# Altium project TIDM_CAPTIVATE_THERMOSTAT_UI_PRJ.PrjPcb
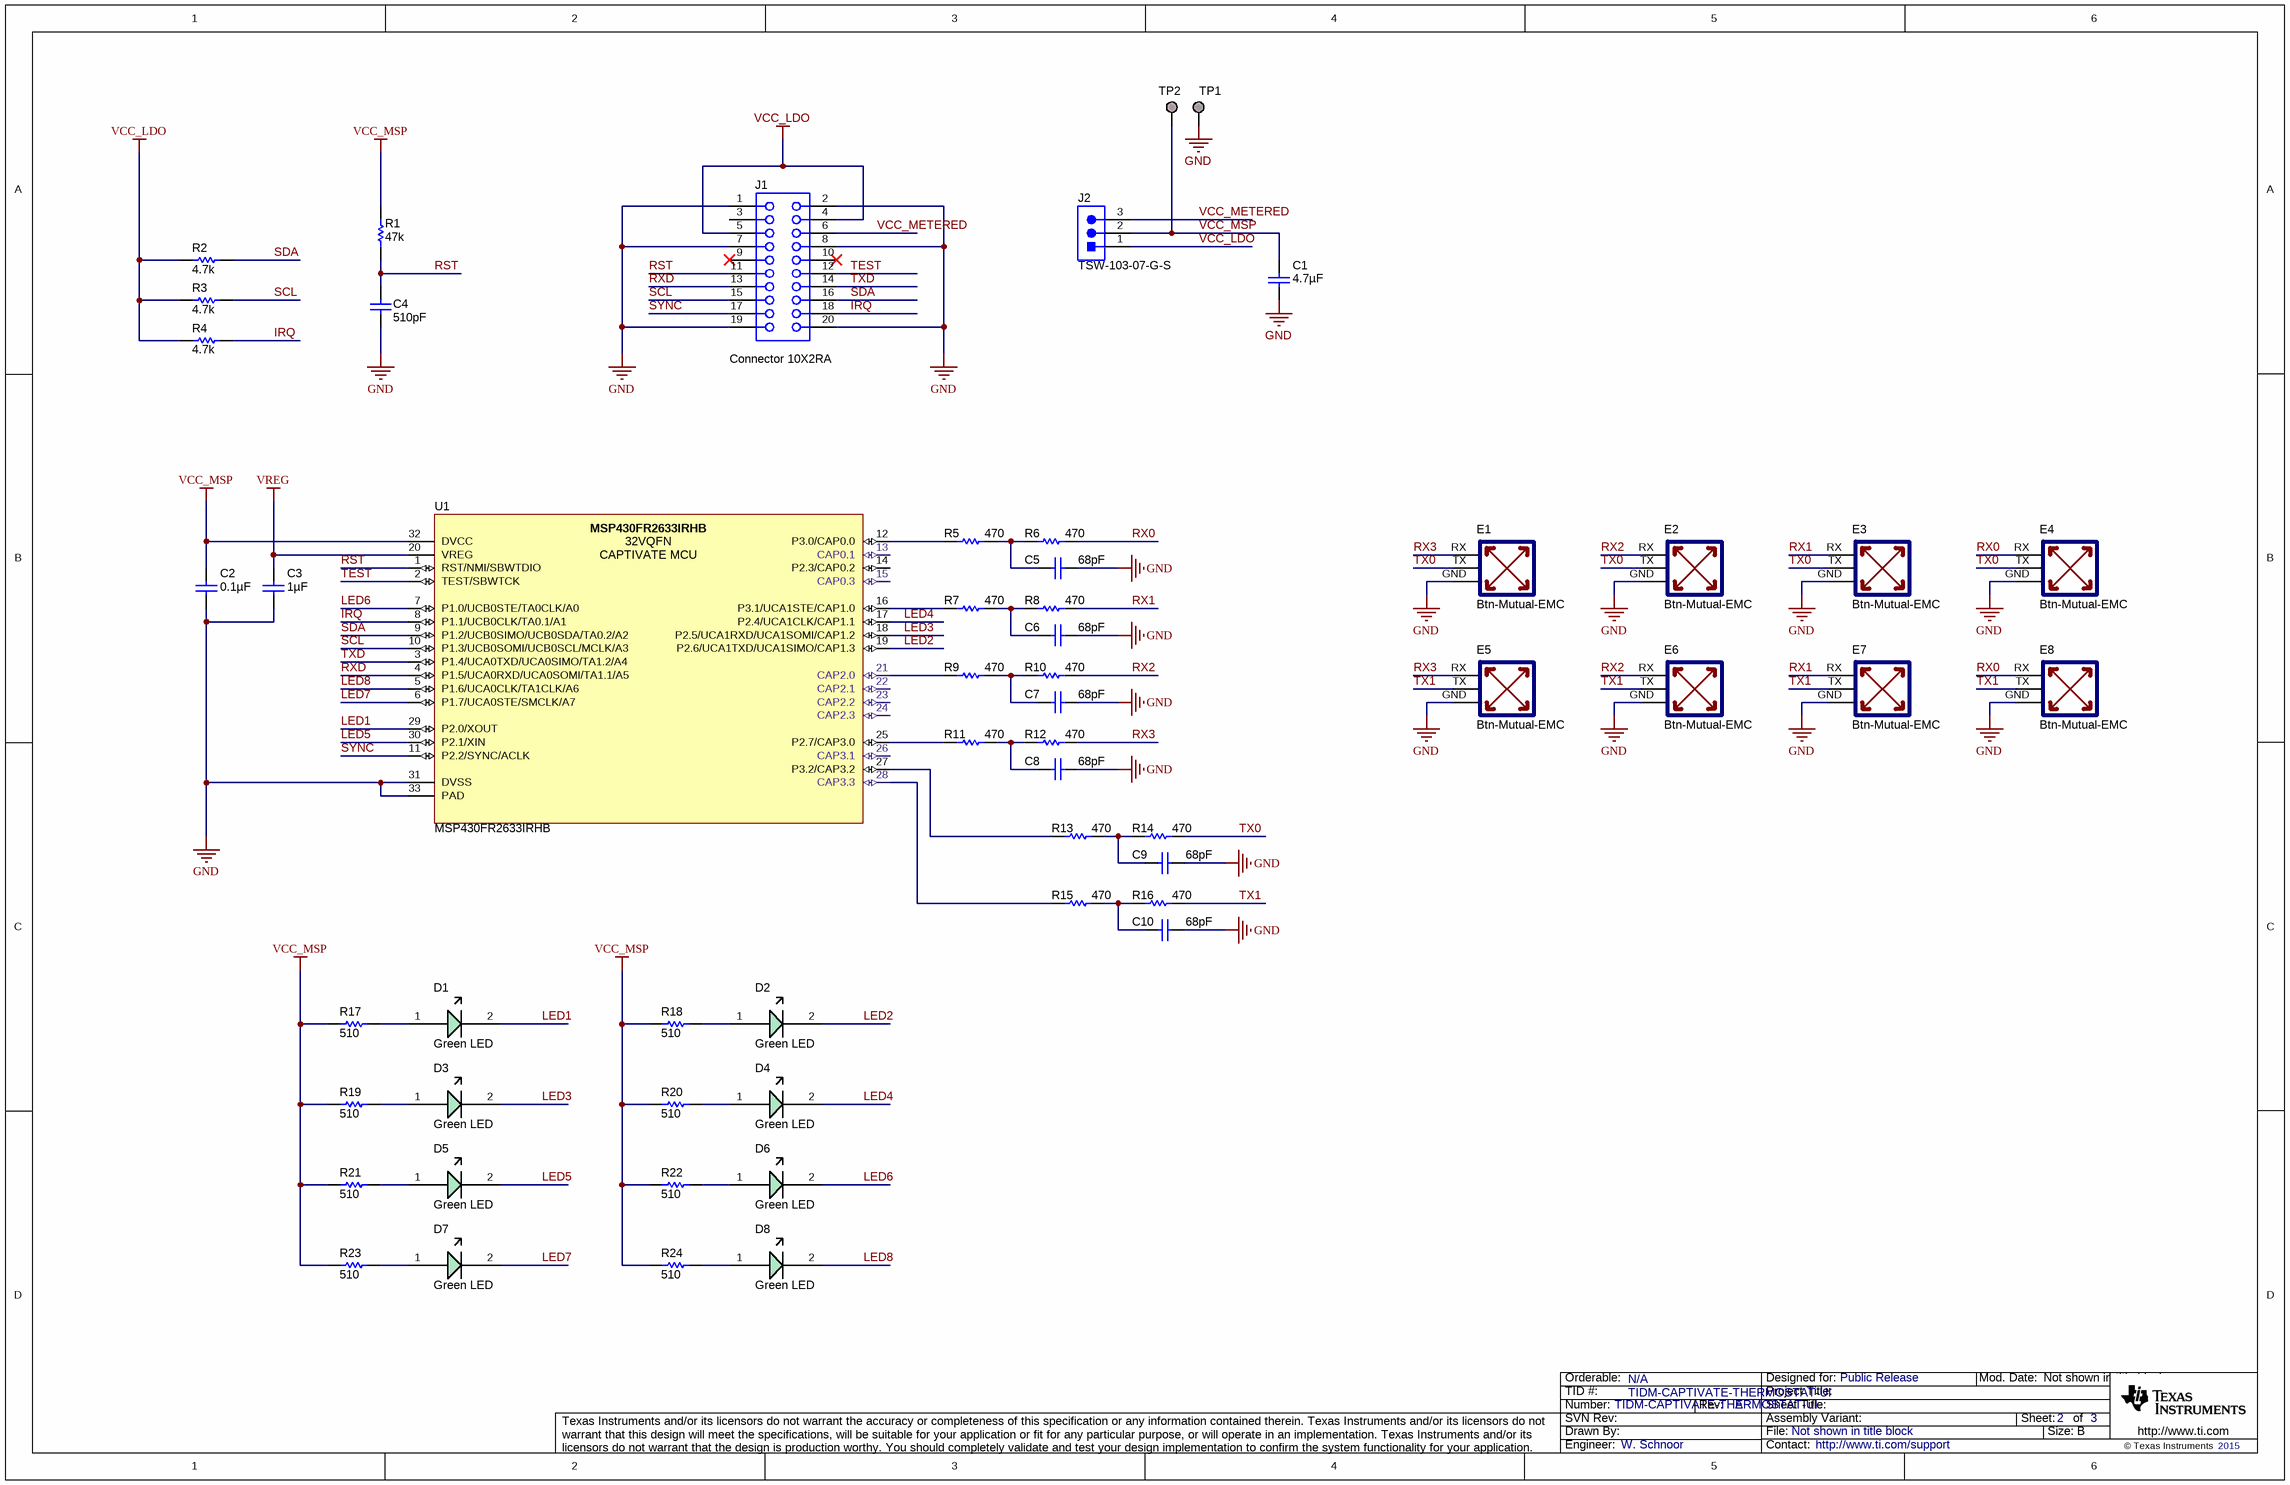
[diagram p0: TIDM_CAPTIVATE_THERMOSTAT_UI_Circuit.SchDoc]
CopyrightYear: 2015; EVM_orderable: N/A; PCB_Layout: W. Schnoor; PCB_Rev: A; PRJ_Customer: Public Release; PRJ_Engineer: W. Schnoor; PRJ_Number: TIDM-CAPTIVATE-THERMOSTAT-UI; SCH_Rev: A; TechSupport: http://www.ti.com/support; TID: TIDM-CAPTIVATE-THERMOSTAT-UI
2 sheets, 61 parts. Net scope: global (net labels, ports and power ports of the same name join across sheets).
Board file: TIDM_CAPTIVATE_THERMOSTAT_UI_PCB.PcbDoc
Sheets:
  TIDM_CAPTIVATE_THERMOSTAT_UI_Circuit.SchDoc
  TIDM_CAPTIVATE_THERMOSTAT_UI_Hardware.SchDoc

## Sheet TIDM_CAPTIVATE_THERMOSTAT_UI_Circuit.SchDoc
size 431 x 279 mm; Date: Not shown in title block; ApprovedBy: Not shown in title block; CheckedBy: Not shown in title block; Author: Not shown in title block; CompanyName: Not shown in title block; Engineer: Not shown in title block; Organization: Not shown in title block; Address1: Not shown in title block; Address2: Not shown in title block; Address3: Not shown in title block; Address4: Not shown in title block; DocumentNumber: 1; Revision: Use project parameter SCH_Rev; SheetNumber: 2; SheetTotal: 3; PageSetup: Record=PageOptions¦CenterHorizontal=True¦CenterVertical=True¦PrintScale=1.00¦XCorrection=1.00¦YCorrection=1.00¦PrintKind=0¦BorderSize=5000000¦LeftOffset=0¦BottomOffset=0¦Orientation=2¦PaperLength=1000¦PaperWidth=1000¦Scale=100¦PaperSource=15¦PrintQuality=600¦MediaType=1¦DitherType=10¦PrintScaleMode=1¦PaperKind=Letter

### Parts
C1  ValueDisplayed: 4.7µF  [0402]  (hidden comment: C1005X5R0J475M050BC)
C2  ValueDisplayed: 0.1µF  [0402]  (hidden comment: C1005X5R0J104K)
C3  ValueDisplayed: 1µF  [0402]  (hidden comment: C1005X5R0J105M)
C4  ValueDisplayed: 510pF  [0402]  (hidden comment: GRM1555C1E511JA01D)
C5  ValueDisplayed: 68pF  [0402]  (hidden comment: GRM1555C1H680JA01D)
C6  ValueDisplayed: 68pF  [0402]  (hidden comment: GRM1555C1H680JA01D)
C7  ValueDisplayed: 68pF  [0402]  (hidden comment: GRM1555C1H680JA01D)
C8  ValueDisplayed: 68pF  [0402]  (hidden comment: GRM1555C1H680JA01D)
C9  ValueDisplayed: 68pF  [0402]  (hidden comment: GRM1555C1H680JA01D)
C10  ValueDisplayed: 68pF  [0402]  (hidden comment: GRM1555C1H680JA01D)
D1  Green LED  [1206_ReverseMount_LED]
D2  Green LED  [1206_ReverseMount_LED]
D3  Green LED  [1206_ReverseMount_LED]
D4  Green LED  [1206_ReverseMount_LED]
D5  Green LED  [1206_ReverseMount_LED]
D6  Green LED  [1206_ReverseMount_LED]
D7  Green LED  [1206_ReverseMount_LED]
D8  Green LED  [1206_ReverseMount_LED]
E1  Btn-Mutual-EMC  [electrode-mutual-highemc-cut-rotated]  (no BOM)
E2  Btn-Mutual-EMC  [electrode-mutual-highemc-cut-rotated]  (no BOM)
E3  Btn-Mutual-EMC  [electrode-mutual-highemc-cut-rotated]  (no BOM)
E4  Btn-Mutual-EMC  [electrode-mutual-highemc-cut-rotated]  (no BOM)
E5  Btn-Mutual-EMC  [electrode-mutual-highemc-cut-rotated]  (no BOM)
E6  Btn-Mutual-EMC  [electrode-mutual-highemc-cut-rotated]  (no BOM)
E7  Btn-Mutual-EMC  [electrode-mutual-highemc-cut-rotated]  (no BOM)
E8  Btn-Mutual-EMC  [electrode-mutual-highemc-cut-rotated]  (no BOM)
J1  Connector 10X2RA  [CONN2X10RA]
J2  TSW-103-07-G-S  [TSW-103-07-G-S]
R1  ValueDisplayed: 47k  [0402]  (hidden comment: CRCW040247K0JNED)
R2  ValueDisplayed: 4.7k  [0402]  (hidden comment: CRCW04024K70JNED)
R3  ValueDisplayed: 4.7k  [0402]  (hidden comment: CRCW04024K70JNED)
R4  ValueDisplayed: 4.7k  [0402]  (hidden comment: CRCW04024K70JNED)
R5  ValueDisplayed: 470  [0402]  (hidden comment: CRCW0402470RJNED)
R6  ValueDisplayed: 470  [0402]  (hidden comment: CRCW0402470RJNED)
R7  ValueDisplayed: 470  [0402]  (hidden comment: CRCW0402470RJNED)
R8  ValueDisplayed: 470  [0402]  (hidden comment: CRCW0402470RJNED)
R9  ValueDisplayed: 470  [0402]  (hidden comment: CRCW0402470RJNED)
R10  ValueDisplayed: 470  [0402]  (hidden comment: CRCW0402470RJNED)
R11  ValueDisplayed: 470  [0402]  (hidden comment: CRCW0402470RJNED)
R12  ValueDisplayed: 470  [0402]  (hidden comment: CRCW0402470RJNED)
R13  ValueDisplayed: 470  [0402]  (hidden comment: CRCW0402470RJNED)
R14  ValueDisplayed: 470  [0402]  (hidden comment: CRCW0402470RJNED)
R15  ValueDisplayed: 470  [0402]  (hidden comment: CRCW0402470RJNED)
R16  ValueDisplayed: 470  [0402]  (hidden comment: CRCW0402470RJNED)
R17  ValueDisplayed: 510  [0402]  (hidden comment: CRCW0402510RJNED)
R18  ValueDisplayed: 510  [0402]  (hidden comment: CRCW0402510RJNED)
R19  ValueDisplayed: 510  [0402]  (hidden comment: CRCW0402510RJNED)
R20  ValueDisplayed: 510  [0402]  (hidden comment: CRCW0402510RJNED)
R21  ValueDisplayed: 510  [0402]  (hidden comment: CRCW0402510RJNED)
R22  ValueDisplayed: 510  [0402]  (hidden comment: CRCW0402510RJNED)
R23  ValueDisplayed: 510  [0402]  (hidden comment: CRCW0402510RJNED)
R24  ValueDisplayed: 510  [0402]  (hidden comment: CRCW0402510RJNED)
TP1  GND  [Mill-Max_2505-2]  (value not drawn)
TP2  VCC_MSP  [Mill-Max_2505-2]  (value not drawn)
U1  MSP430FR2633IRHB  [RHB0032E]

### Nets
GND: C1.2 C2.2 C3.2 C4.2 C5.2 C6.2 C7.2 C8.2 C9.2 C10.2 E1.GND E2.GND E3.GND E4.GND E5.GND E6.GND E7.GND E8.GND J1.1 J1.2 J1.7 J1.8 J1.19 J1.20 TP1.1 U1.31(DVSS) U1.33(PAD)
VCC_LDO: J1.4 J1.5 J2.1 R2.1 R3.1 R4.1
VCC_MSP: C1.1 C2.1 J2.2 R1.2 R17.1 R18.1 R19.1 R20.1 R21.1 R22.1 R23.1 R24.1 TP2.1 U1.32(DVCC)
VREG: C3.1 U1.20(VREG)
IRQ: J1.18 R4.2 U1.8(P1.1/UCB0CLK/TA0.1/A1)
LED1: D1.2(Cathode) U1.29(P2.0/XOUT)
LED2: D2.2(Cathode) U1.19(P2.6/UCA1TXD/UCA1SIMO/CAP1.3)
LED3: D3.2(Cathode) U1.18(P2.5/UCA1RXD/UCA1SOMI/CAP1.2)
LED4: D4.2(Cathode) U1.17(P2.4/UCA1CLK/CAP1.1)
LED5: D5.2(Cathode) U1.30(P2.1/XIN)
LED6: D6.2(Cathode) U1.7(P1.0/UCB0STE/TA0CLK/A0)
LED7: D7.2(Cathode) U1.6(P1.7/UCA0STE/SMCLK/A7)
LED8: D8.2(Cathode) U1.5(P1.6/UCA0CLK/TA1CLK/A6)
RST: C4.1 J1.11 R1.1 U1.1(RST/NMI/SBWTDIO)
RX0: E4.RX E8.RX R6.2
RX1: E3.RX E7.RX R8.2
RX2: E2.RX E6.RX R10.2
RX3: E1.RX E5.RX R12.2
RXD: J1.13 U1.4(P1.5/UCA0RXD/UCA0SOMI/TA1.1/A5)
SCL: J1.15 R3.2 U1.10(P1.3/UCB0SOMI/UCB0SCL/MCLK/A3)
SDA: J1.16 R2.2 U1.9(P1.2/UCB0SIMO/UCB0SDA/TA0.2/A2)
SYNC: J1.17 U1.11(P2.2/SYNC/ACLK)
TEST: J1.12 U1.2(TEST/SBWTCK)
TX0: E1.TX E2.TX E3.TX E4.TX R14.2
TX1: E5.TX E6.TX E7.TX E8.TX R16.2
TXD: J1.14 U1.3(P1.4/UCA0TXD/UCA0SIMO/TA1.2/A4)
VCC_METERED: J1.6 J2.3
NetC5_1: C5.1 R5.2 R6.1
NetC6_1: C6.1 R7.2 R8.1
NetC7_1: C7.1 R9.2 R10.1
NetC8_1: C8.1 R11.2 R12.1
NetC9_1: C9.1 R13.2 R14.1
NetC10_1: C10.1 R15.2 R16.1
NetD1_1: D1.1(Anode) R17.2
NetD2_1: D2.1(Anode) R18.2
NetD3_1: D3.1(Anode) R19.2
NetD4_1: D4.1(Anode) R20.2
NetD5_1: D5.1(Anode) R21.2
NetD6_1: D6.1(Anode) R22.2
NetD7_1: D7.1(Anode) R23.2
NetD8_1: D8.1(Anode) R24.2
NetR5_1: R5.1 U1.12(P3.0/CAP0.0)
NetR7_1: R7.1 U1.16(P3.1/UCA1STE/CAP1.0)
NetR9_1: R9.1 U1.21(CAP2.0)
NetR11_1: R11.1 U1.25(P2.7/CAP3.0)
NetR13_1: R13.1 U1.27(P3.2/CAP3.2)
NetR15_1: R15.1 U1.28(CAP3.3)

Not connected (* = marked no-connect by the designer): J1 3 9* 10*; U1 13(CAP0.1) 14(P2.3/CAP0.2) 15(CAP0.3) 22(CAP2.1) 23(CAP2.2) 24(CAP2.3) 26(CAP3.1)

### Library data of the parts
C1 = C1005X5R0J475M050BC: CAP, CERM, 4.7 µF, 6.3 V, +/- 20%, X5R, 0402; Manufacturer: TDK; Polarized: N; CompType: Capacitor; Value: 4.7uF; U/M: EA; Cap_F: 0.0000047; Tolerance_%: 20; Value1: Unknown; VDC_V: 6.3; Value2: 6.3V; TaMin_C: -55; TaMax_C: 85
C2 = C1005X5R0J104K: CAP, CERM, 0.1 µF, 6.3 V, +/- 10%, X5R, 0402; Manufacturer: TDK; Polarized: N; CompType: Capacitor; Value: 0.1uF; U/M: EA; Cap_F: 0.0000001; Tolerance_%: 10; ESR_ohm: 0.0186; Value1: 0.0186 ohm; VDC_V: 6.3; Value2: 6.3V; TaMin_C: -55; TaMax_C: 85
C3 = C1005X5R0J105M: CAP, CERM, 1 µF, 6.3 V, +/- 20%, X5R, 0402; Manufacturer: TDK; Polarized: N; CompType: Capacitor; Value: 1uF; U/M: EA; Cap_F: 0.000001; Tolerance_%: 20; ESR_ohm: 0.0079; Value1: 0.0079 ohm; VDC_V: 6.3; Value2: 6.3V; TaMin_C: -55; TaMax_C: 85
C4 = GRM1555C1E511JA01D: CAP, CERM, 510 pF, 25 V, +/- 5%, C0G/NP0, 0402; Manufacturer: MuRata; Polarized: N; CompType: Capacitor; Value: 510pF; U/M: EA; Cap_F: 0.00000000051; Tolerance_%: 5; Value1: Unknown; VDC_V: 25; Value2: 25V; TaMin_C: -55; TaMax_C: 125
C5-C10 = GRM1555C1H680JA01D: CAP, CERM, 68 pF, 50 V, +/- 5%, C0G/NP0, 0402; Manufacturer: MuRata; Polarized: N; CompType: Capacitor; Value: 68pF; U/M: EA; Cap_F: 0.000000000068; Tolerance_%: 5; Value1: Unknown; VDC_V: 50; Value2: 50V; TaMin_C: -55; TaMax_C: 125
D1-D8 = 597-6301-607F: LED, Green, SMD, Reverse Mount, 1206; Manufacturer: Dialight; SymbolCreator: a0273983; U/M: EA, IN, or GM; Vf: 2.8V-3.8V
E1-E8 = btn-mutual-emc: Capacitive Button, Mutual, 2-layer, High EMC; Manufacturer: None; SymbolCreator: a0273983; CompType: Electrode; U/M: EA, IN, or GM
J1 = Connector 10X2RA: Connector, Female, 10-Pin, 2 row, Right Angle; Manufacturer: Samtec; PartNumber: SSW-110-22-F-D-RA
J2 = TSW-103-07-G-S: Header, 100mil, 3x1, Gold, TH; Manufacturer: Samtec; SymbolCreator: a0799628; U/M: EA
R1 = CRCW040247K0JNED: RES, 47 k, 5%, 0.063 W, 0402; Manufacturer: Vishay-Dale; CompType: Resistor; Value: 47k; Res_ohm: 47000; Value_Code: 47k0; Tolerance_%: 5; Power_W: 0.063; Value2: 0.063W; VDC_V: 50; TempCo: 200 ppm/C; EIA_Code: E24; U/M: EA
R2-R4 = CRCW04024K70JNED: RES, 4.7 k, 5%, 0.063 W, 0402; Manufacturer: Vishay-Dale; CompType: Resistor; Value: 4.7k; Res_ohm: 4700; Value_Code: 4k70; Tolerance_%: 5; Power_W: 0.063; Value2: 0.063W; VDC_V: 50; TempCo: 200 ppm/C; EIA_Code: E24; U/M: EA
R5-R16 = CRCW0402470RJNED: RES, 470, 5%, 0.063 W, 0402; Manufacturer: Vishay-Dale; CompType: Resistor; Value: 470; Value_Code: 470R; Tolerance_%: 5; Power_W: 0.063; Value2: 0.063W; VDC_V: 50; TempCo: 200 ppm/C; EIA_Code: E24; U/M: EA
R17-R24 = CRCW0402510RJNED: RES, 510, 5%, 0.063 W, 0402; Manufacturer: Vishay-Dale; CompType: Resistor; Value: 510; Value_Code: 510R; Tolerance_%: 5; Power_W: 0.063; Value2: 0.063W; VDC_V: 50; TempCo: 200 ppm/C; EIA_Code: E24; U/M: EA
TP1 TP2 = 2505-2-00-44-00-00-07-0: PCB Pin, Swage Mount, TH; Manufacturer: Mill-Max; CompType: PCB Pin
U1 = MSP430FR2633IRHB: MSP430 Captivate Microcontroller; Manufacturer: Texas Instruments; SymbolCreator: W. Schnoor; CompType: IC; U/M: EA, IN, or GM

## Sheet TIDM_CAPTIVATE_THERMOSTAT_UI_Hardware.SchDoc
size 431 x 279 mm; Date: Not shown in title block; ApprovedBy: Not shown in title block; CheckedBy: Not shown in title block; Author: Not shown in title block; CompanyName: Not shown in title block; Engineer: Not shown in title block; Organization: Not shown in title block; Address1: Not shown in title block; Address2: Not shown in title block; Address3: Not shown in title block; Address4: Not shown in title block; DocumentNumber: 1; Revision: Use project parameter SCH_Rev; SheetNumber: 3; SheetTotal: 3; PageSetup: Record=PageOptions¦CenterHorizontal=True¦CenterVertical=True¦PrintScale=1.00¦XCorrection=1.00¦YCorrection=1.00¦PrintKind=0¦BorderSize=5000000¦LeftOffset=0¦BottomOffset=0¦Orientation=2¦PaperLength=1000¦PaperWidth=1000¦Scale=100¦PaperSource=15¦PrintQuality=600¦MediaType=1¦DitherType=10¦PaperKind=Letter¦PrintScaleMode=1
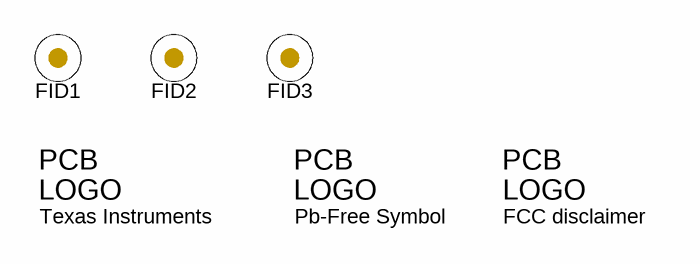
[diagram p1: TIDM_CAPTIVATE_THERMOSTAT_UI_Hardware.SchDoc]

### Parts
FID1  Fiducial  [Fiducial10-20]  (value not drawn)
FID2  Fiducial  [Fiducial10-20]  (value not drawn)
FID3  Fiducial  [Fiducial10-20]  (value not drawn)
Logo1  Texas Instruments  [TI_Horizontal_Overlay_Medium]  (no BOM)
Logo2  Pb-Free Symbol  [Pb-Free_Overlay_Small]  (no BOM)
Logo3  FCC disclaimer  [FCC_disclaimer]  (no BOM)

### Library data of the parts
FID1-FID3 = Fiducial: Fiducial mark.  There is nothing to buy or mount.; SymbolCreator: codlsc
Logo1 = TI_Logo: Texas Instrument Corporate Signature; SymbolCreator: a0412235
Logo2 = Pb-Free: SymbolCreator: a0412235
Logo3 = FCC_disclaimer: SymbolCreator: codlsc

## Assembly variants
TI Design: not fitted C9 C10; alternate parts R6 -> CRCW04020000Z0ED, R8 -> CRCW04020000Z0ED, R10 -> CRCW04020000Z0ED, R12 -> CRCW04020000Z0ED, R14 -> CRCW04020000Z0ED, R16 -> CRCW04020000Z0ED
